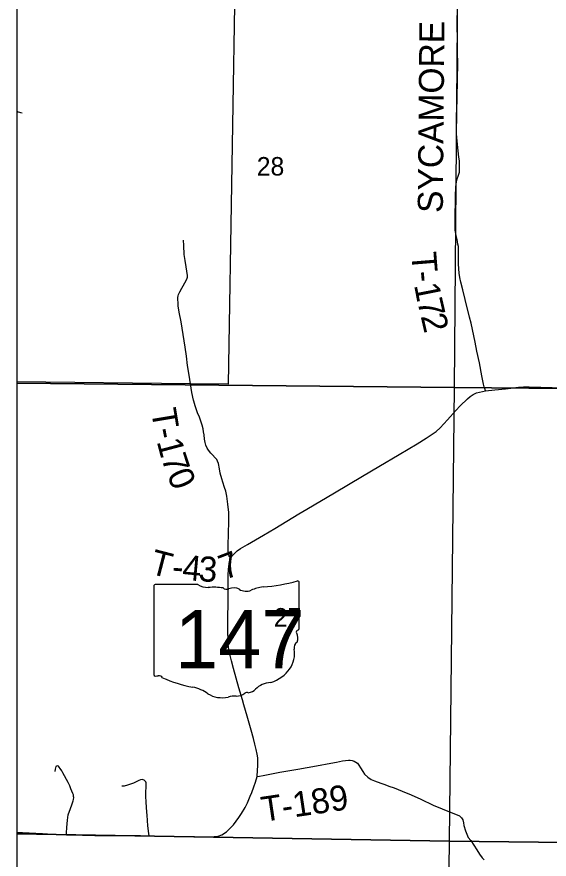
# Model space of a CAD drawing. Extents: x 0 to 34, y 0 to 22.
# Drawn here: x 2.1 to 3.307, y 15.399 to 17.307 of the extents above; entities that cross this region are included whole.
import ezdxf

# ---------------------------------------------------------------- set-up
doc = ezdxf.new("R2010")
doc.units = 0
for name, color, linetype in [('GM_X_Corporation', 7, 'Continuous'), ('GM_X_Section_Text', 7, 'Continuous'), ('GM_X_State_Location', 7, 'Continuous'), ('GM_X_State_Route', 7, 'Continuous'), ('GM_X_State_Shield', 7, 'Continuous'), ('GM_X_Township_Road', 7, 'Continuous'), ('GM_X_Township_Road_Text', 7, 'Continuous'), ('GM_X_Township_Text', 7, 'Continuous'), ('SH_Data', 7, 'Continuous')]:
    doc.layers.add(name, color=color, linetype=linetype)

msp = doc.modelspace()

# ---------------------------------------------------------------- linework, layer by layer
at = {"layer": 'GM_X_Corporation'}
for points in [[(2.1, 17.4968), (2.1, 16.4774), (3.0928, 16.4681), (3.1011, 17.4796)], [(3.1011, 17.4796), (4.1176, 17.4733), (4.1025, 16.4586), (3.0928, 16.4681)], [(2.1, 16.4774), (2.1, 15.4568), (3.0813, 15.4398), (3.0928, 16.4681)], [(4.1025, 16.4586), (4.0887, 15.4288), (3.0813, 15.4398), (3.0928, 16.4681)], [(2.1, 15.4568), (2.1, 14.4279), (3.0687, 14.4122), (3.0813, 15.4398)], [(3.0813, 15.4398), (4.0887, 15.4288), (4.0718, 14.4088), (3.0687, 14.4122)]]:
    msp.add_lwpolyline(points, close=True, dxfattribs=at)
at = {"layer": 'GM_X_State_Route'}
for points in [[(2.2036, 15.4551), (2.213, 15.4544), (2.2258, 15.4542), (2.2487, 15.4535), (2.2772, 15.4531), (2.3156, 15.4527), (2.345, 15.4527), (2.3807, 15.4526), (2.4003, 15.4524), (2.5028, 15.4503), (2.5371, 15.4496), (2.5475, 15.4505), (2.5565, 15.4515), (2.5651, 15.4547), (2.5752, 15.4613), (2.5854, 15.4707), (2.5911, 15.4774), (2.5976, 15.4857), (2.6032, 15.4935), (2.6095, 15.5026), (2.6178, 15.5165), (2.6229, 15.5267), (2.6264, 15.5347), (2.6295, 15.5418), (2.6328, 15.5506), (2.6376, 15.5629), (2.6412, 15.5741), (2.6447, 15.5869), (2.6461, 15.6011), (2.6469, 15.6105), (2.6468, 15.6215), (2.6462, 15.6288), (2.6449, 15.6372), (2.6427, 15.6475), (2.6394, 15.66), (2.6364, 15.6729), (2.6313, 15.6915), (2.622, 15.7236), (2.6149, 15.7486), (2.6119, 15.76), (2.6035, 15.7875), (2.5914, 15.8313), (2.5869, 15.8484), (2.5825, 15.867), (2.5803, 15.8787), (2.5796, 15.886), (2.579, 15.8997), (2.5786, 15.9113), (2.5786, 15.9328), (2.5793, 15.9925), (2.5796, 16.0416), (2.58, 16.0561), (2.5804, 16.0618), (2.5814, 16.0688), (2.5826, 16.0739), (2.5854, 16.0814), (2.5886, 16.0865), (2.5952, 16.0934), (2.6, 16.0976), (2.6071, 16.1027), (2.623, 16.1123), (2.6594, 16.1332), (2.685, 16.1487), (2.7398, 16.1815), (2.7575, 16.1919), (2.8202, 16.2289), (2.8841, 16.2669), (2.9211, 16.289), (2.9672, 16.3162), (2.9877, 16.3284), (3.0082, 16.3405), (3.0281, 16.3527), (3.0397, 16.3602), (3.0509, 16.3684), (3.0598, 16.3762), (3.0763, 16.3943), (3.0955, 16.4155), (3.1056, 16.426), (3.122, 16.4424), (3.1283, 16.4473), (3.1352, 16.4517), (3.1427, 16.4556), (3.1492, 16.4575), (3.1629, 16.4603), (3.1842, 16.4623), (3.2083, 16.4651), (3.2373, 16.4683), (3.2493, 16.4691), (3.2617, 16.469), (3.3407, 16.467)], [(2.1, 15.46), (2.1129, 15.4595), (2.158, 15.4576), (2.1817, 15.4562), (2.1998, 15.4553), (2.2036, 15.4551)]]:
    msp.add_lwpolyline(points, dxfattribs=at)
at = {"layer": 'GM_X_State_Shield'}
for p, q in [((2.4108, 16.0177), (2.4108, 15.8176)), ((2.5105, 16.0212), (2.414, 16.0212)), ((2.7403, 15.9215), (2.7403, 16.0261)), ((2.7403, 15.9215), (2.7403, 15.9215))]:
    msp.add_line(p, q, dxfattribs=at)
for centre, major_axis, start_param, end_param in [((2.6229, 16.294), (0.3495, 0), 4.814394, 5.042369), ((2.7367, 16.0266), (0.00367, 0), 6.141152, 7.989035), ((2.4145, 16.0182), (0.00382, 0), 1.712693, 3.28349), ((2.5335, 16.0444), (0.037, 0), 4.042523, 4.731795), ((2.5458, 15.9088), (0.133, 0), 1.404758, 1.657858), ((2.576, 16.0192), (0.0107, 0), 3.836095, 5.185415), ((2.5917, 15.9961), (0.0222, 0), 0.950623, 2.079405), ((2.6203, 16.0278), (0.0267, 0), 4.081561, 5.145723), ((2.6675, 15.9601), (0.0703, 0), 1.699011, 2.107814), ((2.7395, 15.9138), (0.00568, 0), 1.883978, 3.671073), ((2.7364, 15.9211), (0.00393, 0), 5.05454, 6.418171), ((2.7034, 15.9005), (0.0341, 0), 5.934695, 6.695948), ((2.6425, 15.8643), (0.0874, 0), 5.101752, 6.440018), ((2.7535, 15.8776), (0.0248, 0), 2.387724, 3.262537), ((2.4146, 15.8172), (0.00385, 0), 3.00124, 4.508301), ((2.4151, 15.8377), (0.0294, 0), 4.665946, 4.897461), ((2.4212, 15.8061), (0.0106, 0), 0.519207, 1.627899), ((2.555, 15.9859), (0.2524, 0), 4.195997, 4.488961), ((2.6794, 15.7614), (0.0479, 0), 1.647645, 2.488434), ((2.4797, 15.7277), (0.079, 0), 0.823519, 1.323587), ((2.6187, 15.7982), (0.0282, 0), 4.937069, 5.64225), ((2.5652, 15.8051), (0.0501, 0), 4.026481, 4.996735), ((2.5941, 15.7359), (0.0412, 0), 1.495662, 1.94098), ((2.5978, 15.7901), (0.0267, 0), 4.691044, 5.507374), ((2.6219, 15.7707), (0.00752, 0), 1.147584, 2.315152)]:
    msp.add_ellipse(centre, major_axis=major_axis, ratio=0.8, start_param=start_param, end_param=end_param, dxfattribs=at)
at = {"layer": 'GM_X_Township_Road'}
for points in [[(3.1629, 16.4603), (3.1611, 16.4657), (3.1598, 16.4696), (3.1586, 16.475), (3.1546, 16.4944), (3.1489, 16.524), (3.1435, 16.5503), (3.1392, 16.5705), (3.1301, 16.6135), (3.1264, 16.6272), (3.1165, 16.6668), (3.1114, 16.6891), (3.1068, 16.7065), (3.1046, 16.7169), (3.1031, 16.7266), (3.1019, 16.7468), (3.1017, 16.7708), (3.1014, 16.7826), (3.1013, 16.7875), (3.1003, 16.7925), (3.0984, 16.8033), (3.0962, 16.8123), (3.0941, 16.8245), (3.0938, 16.834), (3.0938, 16.8457), (3.0937, 16.8646), (3.0945, 16.8831), (3.095, 16.9069), (3.0953, 16.916), (3.0957, 16.9224), (3.0964, 16.9282), (3.0972, 16.9334), (3.0987, 16.9402), (3.1007, 16.9465), (3.1035, 16.9556), (3.1041, 16.9628), (3.1042, 16.9694), (3.1036, 16.9814), (3.1027, 16.9893), (3.0996, 17.0182), (3.0974, 17.0424), (3.0971, 17.0659), (3.097, 17.0818), (3.0986, 17.1183), (3.0993, 17.1692), (3.0998, 17.1984), (3.0996, 17.2298), (3.099, 17.2615), (3.0984, 17.2836), (3.0984, 17.2954), (3.0983, 17.3106)], [(2.1, 17.0938), (2.1005, 17.0934), (2.1027, 17.0923), (2.1059, 17.0913), (2.1086, 17.0905), (2.1119, 17.0897)], [(2.501, 16.4393), (2.4972, 16.4564), (2.494, 16.4757), (2.4909, 16.4958), (2.4873, 16.5177), (2.4844, 16.5387), (2.4815, 16.5595), (2.4726, 16.6167), (2.4684, 16.6385), (2.4661, 16.6526), (2.4655, 16.6602), (2.4651, 16.6662), (2.4653, 16.6715), (2.4659, 16.6751), (2.4667, 16.6782), (2.4699, 16.6847), (2.4742, 16.6925), (2.4839, 16.7099), (2.486, 16.7152), (2.4867, 16.7178), (2.4872, 16.7213), (2.4839, 16.7408), (2.4815, 16.7558), (2.4798, 16.7689), (2.479, 16.7892), (2.4777, 16.8018)], [(2.5854, 16.0814), (2.5815, 16.0855), (2.58, 16.0922), (2.5791, 16.0979), (2.579, 16.1068), (2.5802, 16.1401), (2.5804, 16.1614), (2.5804, 16.1845), (2.5788, 16.2037), (2.576, 16.2213), (2.5737, 16.2327), (2.571, 16.2416), (2.5672, 16.253), (2.5648, 16.2606), (2.5612, 16.2734), (2.5596, 16.2835), (2.5573, 16.2956), (2.5554, 16.301), (2.5535, 16.3046), (2.54, 16.319), (2.5343, 16.3257), (2.5315, 16.3302), (2.5284, 16.3369), (2.527, 16.3431), (2.5259, 16.3504), (2.5251, 16.3607), (2.5237, 16.3677), (2.5225, 16.374), (2.52, 16.3827), (2.5174, 16.3916), (2.5142, 16.4006), (2.51, 16.4104), (2.5073, 16.4171), (2.5041, 16.426), (2.5015, 16.4371), (2.501, 16.4393)], [(2.213, 15.4544), (2.2129, 15.4592), (2.2137, 15.4707), (2.2141, 15.4791), (2.2147, 15.4878), (2.2167, 15.4994), (2.2216, 15.5142), (2.2246, 15.5224), (2.2263, 15.5272), (2.2276, 15.5311), (2.2283, 15.5346), (2.2289, 15.5388), (2.2288, 15.5416), (2.2282, 15.5452), (2.2272, 15.5479), (2.2227, 15.5583), (2.2199, 15.5652), (2.2167, 15.5728), (2.2128, 15.5798), (2.2081, 15.5882), (2.2043, 15.5951), (2.2019, 15.5995), (2.1985, 15.6049), (2.1959, 15.608), (2.1942, 15.6098), (2.1919, 15.6106), (2.1898, 15.6101), (2.1883, 15.609), (2.1875, 15.6065), (2.1867, 15.6029), (2.1862, 15.5981)], [(2.6447, 15.5869), (2.6503, 15.5876), (2.6586, 15.589), (2.6741, 15.5918), (2.6962, 15.5962), (2.7145, 15.5996), (2.7374, 15.6034), (2.7587, 15.607), (2.7797, 15.6109), (2.8118, 15.6168), (2.8246, 15.6192), (2.8385, 15.6221), (2.8523, 15.6239), (2.8563, 15.6239), (2.8608, 15.6227), (2.8649, 15.6213), (2.869, 15.619), (2.8722, 15.6164), (2.8755, 15.6122), (2.879, 15.6065), (2.8844, 15.5981), (2.8886, 15.592), (2.8957, 15.5847), (2.9033, 15.5801), (2.9108, 15.5768), (2.9172, 15.5742), (2.9276, 15.5705), (2.9343, 15.5681), (2.9436, 15.5649), (2.9556, 15.5606), (2.9738, 15.5537), (2.9939, 15.5451), (3.0164, 15.5354), (3.0441, 15.522), (3.0649, 15.5131), (3.0885, 15.5034), (3.0987, 15.4994), (3.1039, 15.4972), (3.1084, 15.4932), (3.1116, 15.4881), (3.1129, 15.4818), (3.1137, 15.4759), (3.1175, 15.4633), (3.1236, 15.4483), (3.1295, 15.4415), (3.1429, 15.4206), (3.1495, 15.4107), (3.1555, 15.4026), (3.1597, 15.3977)], [(2.4003, 15.4524), (2.3996, 15.4576), (2.3973, 15.4751), (2.3954, 15.4988), (2.3948, 15.5061), (2.3936, 15.5284), (2.3924, 15.5421), (2.3922, 15.551), (2.393, 15.5634), (2.3932, 15.5681), (2.3934, 15.572), (2.3923, 15.5746), (2.3906, 15.5768), (2.3886, 15.5783), (2.3863, 15.5793), (2.3843, 15.5795), (2.3803, 15.579), (2.3764, 15.5776), (2.3723, 15.5756), (2.3645, 15.5718), (2.358, 15.569), (2.351, 15.5666), (2.3434, 15.565), (2.3379, 15.5649)]]:
    msp.add_lwpolyline(points, dxfattribs=at)
at = {"layer": 'GM_X_Township_Text'}
msp.add_line((2.1, 19.1775), (2.1, 16.4804), dxfattribs=at)
msp.add_lwpolyline([(2.6249, 19.1744), (2.6223, 19.0497), (2.622, 19.0358), (2.6202, 18.9481), (2.604, 17.9706), (2.6039, 17.9669), (2.5791, 16.4754), (2.4938, 16.4762), (2.1, 16.4804), (2.1, 14.1), (7.1227, 14.1)], dxfattribs=at)
at = {"layer": 'SH_Data'}
msp.add_line((2.1, 20.9), (2.1, 14.1), dxfattribs=at)

# ---------------------------------------------------------------- texts
at = {"layer": 'GM_X_Section_Text'}
for s, p in [('28', (2.6442, 16.9479)), ('27', (2.6829, 15.9262))]:
    msp.add_text(s, height=0.04186, rotation=0, dxfattribs=at).set_placement(p)
at = {"layer": 'GM_X_State_Location'}
for s in ['s', 'r']:
    msp.add_text(s, height=0.000189, dxfattribs=at).set_placement((2.5718, 15.9044))
msp.add_text('147', height=0.000189, rotation=0, dxfattribs=at).set_placement((2.505, 15.8906))
at = {"layer": 'GM_X_State_Shield'}
msp.add_text('147', height=0.13184, dxfattribs=at).set_placement((2.4586, 15.8317))
at = {"layer": 'GM_X_Township_Road_Text'}
for s, height, rotation, p in [('SYCAMORE', 0.05682, 89.5094, (3.066, 16.8631)), ('T', 0.0568, 274.6291, (2.9942, 16.7726)), ('-', 0.0568, 275.0175, (2.9976, 16.7298)), ('1', 0.0568, 281.1453, (3.0006, 16.7)), ('7', 0.0568, 282.8759, (3.0078, 16.6638)), ('2', 0.0568, 282.9556, (3.0156, 16.6296)), ('T', 0.0568, 279.406, (2.4043, 16.4161)), ('-', 0.0568, 281.049, (2.4116, 16.3724)), ('1', 0.0568, 284.8367, (2.417, 16.3456)), ('7', 0.0568, 288.2626, (2.427, 16.3082)), ('0', 0.0568, 292.5189, (2.4396, 16.2706)), ('T', 0.0568, 345.4482, (2.3988, 16.0468)), ('4', 0.0568, 354.6845, (2.4738, 16.0326)), ('3', 0.0568, 356.7672, (2.5109, 16.0292)), ('7', 0.0568, 20.9784, (2.5715, 16.0312)), ('-', 0.0568, 355.5557, (2.4507, 16.0344)), ('T-189', 0.05682, 8.4483, (2.6586, 15.4836))]:
    msp.add_text(s, height=height, rotation=rotation, dxfattribs=at).set_placement(p)

doc.saveas('drawing.dxf')
